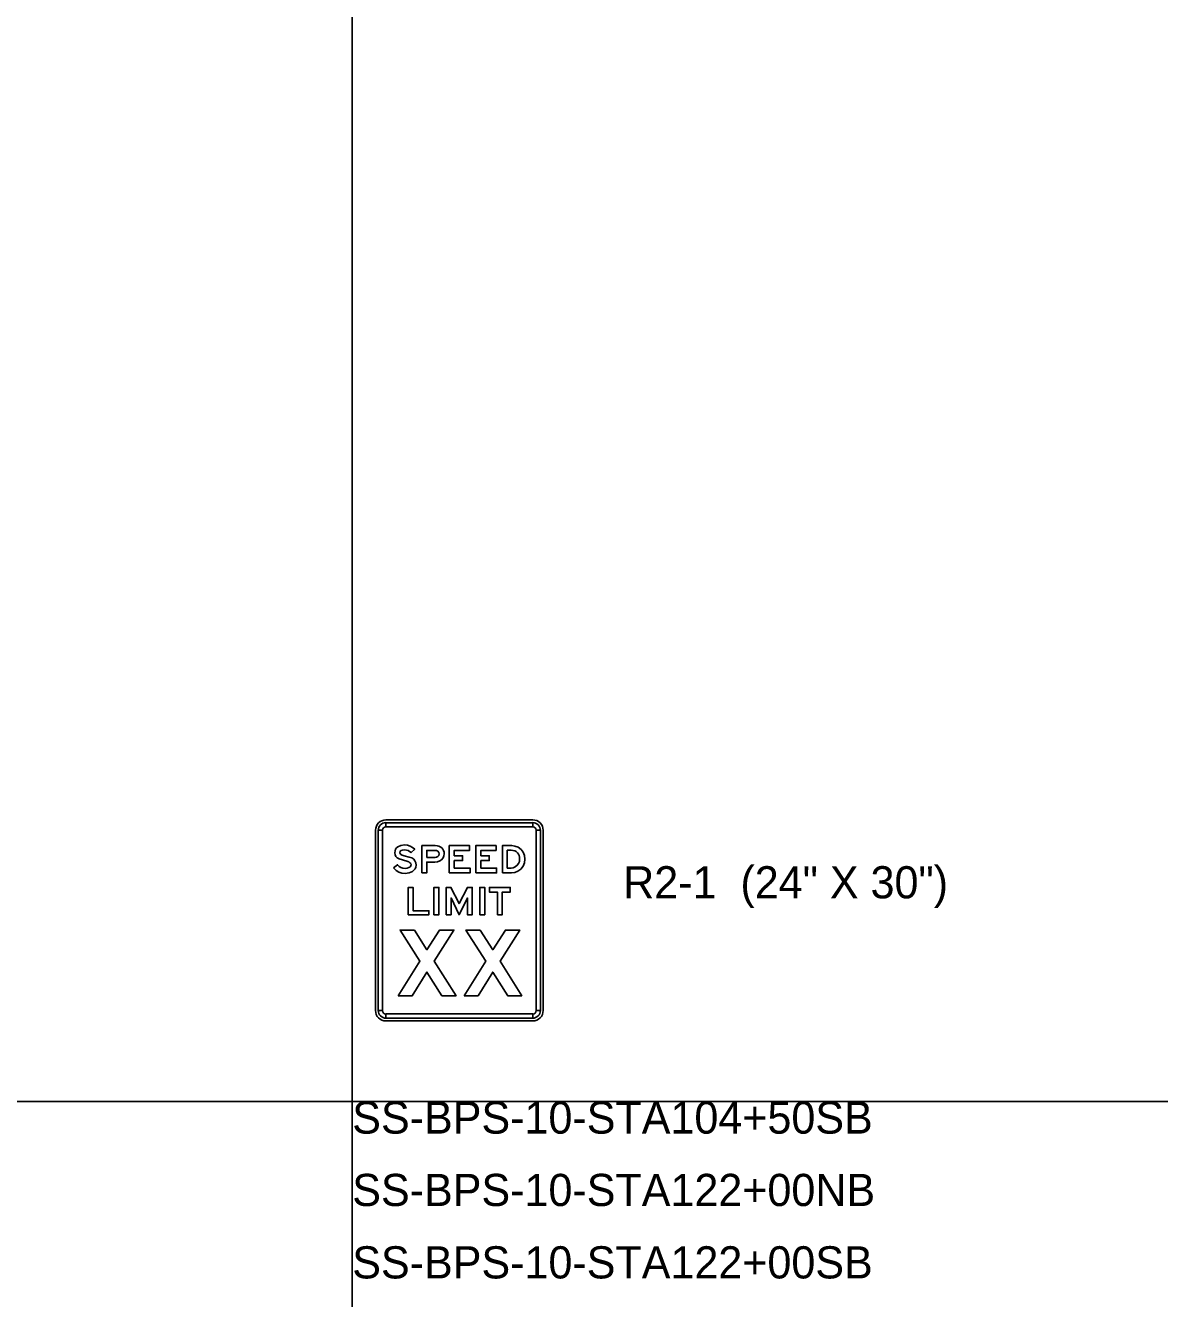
# Model space of a CAD drawing. Extents: x 1001568 to 1002149, y 1840825 to 1841423.
# Drawn here: x 1001914.59 to 1001928.68, y 1841079.02 to 1841094.84 of the extents above; entities that cross this region are included whole.
import ezdxf

# ---------------------------------------------------------------- set-up
doc = ezdxf.new("R2010")
doc.units = 0
for name, color, linetype in [('40', 7, 'Continuous'), ('R_No Plot', 7, 'Continuous'), ('SIGNS', 7, 'Continuous')]:
    doc.layers.add(name, color=color, linetype=linetype)

msp = doc.modelspace()

# ---------------------------------------------------------------- linework, layer by layer
at = {"layer": 'R_No Plot'}
for p, q in [((1001918.65, 1841110.667), (1001918.65, 1841048.127)), ((1001890.65, 1841081.469), (1001982.133, 1841081.469))]:
    msp.add_line(p, q, dxfattribs=at)
at = {"layer": 'SIGNS'}
for p, q in [((1001920.892, 1841084.969), (1001919.069, 1841084.969)), ((1001919.069, 1841084.882), (1001919.069, 1841084.934)), ((1001920.892, 1841084.934), (1001920.892, 1841084.882)), ((1001918.939, 1841084.839), (1001918.939, 1841082.599)), ((1001918.973, 1841084.839), (1001919.025, 1841084.839)), ((1001920.935, 1841084.839), (1001920.987, 1841084.839)), ((1001921.022, 1841082.599), (1001921.022, 1841084.839)), ((1001919.025, 1841082.599), (1001918.973, 1841082.599)), ((1001919.069, 1841082.504), (1001919.069, 1841082.556)), ((1001920.892, 1841082.556), (1001920.892, 1841082.504)), ((1001920.987, 1841082.599), (1001920.935, 1841082.599)), ((1001919.069, 1841082.469), (1001920.892, 1841082.469))]:
    msp.add_line(p, q, dxfattribs=at)
for points in [[(1001920.892, 1841084.934), (1001919.069, 1841084.934), (1001919.069, 1841084.882), (1001920.892, 1841084.882), (1001920.892, 1841084.934), (1001920.892, 1841084.934)], [(1001918.973, 1841084.839), (1001918.973, 1841082.599), (1001919.025, 1841082.599), (1001919.025, 1841084.839), (1001918.973, 1841084.839), (1001918.973, 1841084.839)], [(1001920.987, 1841082.599), (1001920.987, 1841084.839), (1001920.935, 1841084.839), (1001920.935, 1841082.599), (1001920.987, 1841082.599), (1001920.987, 1841082.599)], [(1001919.164, 1841084.371), (1001919.194, 1841084.341), (1001919.227, 1841084.32), (1001919.265, 1841084.307), (1001919.307, 1841084.303), (1001919.355, 1841084.309), (1001919.397, 1841084.328), (1001919.417, 1841084.343), (1001919.431, 1841084.361), (1001919.439, 1841084.382), (1001919.442, 1841084.405), (1001919.439, 1841084.434), (1001919.429, 1841084.458), (1001919.413, 1841084.479), (1001919.39, 1841084.495), (1001919.356, 1841084.507), (1001919.293, 1841084.523), (1001919.27, 1841084.53), (1001919.254, 1841084.539), (1001919.244, 1841084.549), (1001919.241, 1841084.561), (1001919.245, 1841084.576), (1001919.255, 1841084.587), (1001919.273, 1841084.594), (1001919.298, 1841084.596), (1001919.322, 1841084.594), (1001919.343, 1841084.588), (1001919.363, 1841084.577), (1001919.38, 1841084.562), (1001919.427, 1841084.603), (1001919.4, 1841084.627), (1001919.37, 1841084.643), (1001919.337, 1841084.653), (1001919.301, 1841084.657), (1001919.255, 1841084.651), (1001919.218, 1841084.634), (1001919.201, 1841084.62), (1001919.189, 1841084.603), (1001919.182, 1841084.583), (1001919.179, 1841084.561), (1001919.182, 1841084.536), (1001919.192, 1841084.515), (1001919.209, 1841084.497), (1001919.231, 1841084.483), (1001919.328, 1841084.454), (1001919.351, 1841084.446), (1001919.367, 1841084.436), (1001919.377, 1841084.425), (1001919.38, 1841084.412), (1001919.379, 1841084.401), (1001919.374, 1841084.391), (1001919.365, 1841084.383), (1001919.353, 1841084.376), (1001919.331, 1841084.369), (1001919.306, 1841084.366), (1001919.278, 1841084.369), (1001919.254, 1841084.377), (1001919.233, 1841084.391), (1001919.214, 1841084.411)], [(1001919.855, 1841084.309), (1001920.113, 1841084.309), (1001920.113, 1841084.369), (1001919.918, 1841084.369), (1001919.918, 1841084.463), (1001920.021, 1841084.463), (1001920.021, 1841084.523), (1001919.918, 1841084.523), (1001919.918, 1841084.59), (1001920.107, 1841084.59), (1001920.107, 1841084.65), (1001919.855, 1841084.65)], [(1001920.185, 1841084.309), (1001920.443, 1841084.309), (1001920.443, 1841084.369), (1001920.248, 1841084.369), (1001920.248, 1841084.463), (1001920.351, 1841084.463), (1001920.351, 1841084.523), (1001920.248, 1841084.523), (1001920.248, 1841084.59), (1001920.437, 1841084.59), (1001920.437, 1841084.65), (1001920.185, 1841084.65)], [(1001919.345, 1841083.789), (1001919.602, 1841083.789), (1001919.602, 1841083.84), (1001919.406, 1841083.84), (1001919.406, 1841084.129), (1001919.345, 1841084.129)], [(1001919.664, 1841083.789), (1001919.726, 1841083.789), (1001919.726, 1841084.129), (1001919.664, 1841084.129)], [(1001919.817, 1841083.789), (1001919.877, 1841083.789), (1001919.877, 1841083.998), (1001919.977, 1841083.789), (1001920.08, 1841083.998), (1001920.08, 1841083.789), (1001920.14, 1841083.789), (1001920.14, 1841084.129), (1001920.08, 1841084.129), (1001919.977, 1841083.928), (1001919.876, 1841084.129), (1001919.817, 1841084.129)], [(1001920.234, 1841083.789), (1001920.296, 1841083.789), (1001920.296, 1841084.129), (1001920.234, 1841084.129)], [(1001920.454, 1841083.789), (1001920.514, 1841083.789), (1001920.514, 1841084.072), (1001920.613, 1841084.072), (1001920.613, 1841084.129), (1001920.355, 1841084.129), (1001920.355, 1841084.072), (1001920.454, 1841084.072)], [(1001919.222, 1841082.782), (1001919.396, 1841082.782), (1001919.578, 1841083.076), (1001919.764, 1841082.782), (1001919.939, 1841082.782), (1001919.668, 1841083.213), (1001919.912, 1841083.599), (1001919.735, 1841083.599), (1001919.578, 1841083.355), (1001919.422, 1841083.599), (1001919.245, 1841083.599), (1001919.491, 1841083.213)], [(1001920.039, 1841082.782), (1001920.213, 1841082.782), (1001920.396, 1841083.076), (1001920.581, 1841082.782), (1001920.756, 1841082.782), (1001920.486, 1841083.213), (1001920.73, 1841083.599), (1001920.552, 1841083.599), (1001920.396, 1841083.355), (1001920.239, 1841083.599), (1001920.062, 1841083.599), (1001920.308, 1841083.213)], [(1001919.069, 1841082.504), (1001920.892, 1841082.504), (1001920.892, 1841082.556), (1001919.069, 1841082.556), (1001919.069, 1841082.504), (1001919.069, 1841082.504)]]:
    msp.add_lwpolyline(points, close=True, dxfattribs=at)
for points in [[(1001919.515, 1841084.309), (1001919.575, 1841084.309), (1001919.575, 1841084.445), (1001919.674, 1841084.445), (1001919.708, 1841084.448), (1001919.737, 1841084.458), (1001919.76, 1841084.474), (1001919.778, 1841084.496), (1001919.789, 1841084.522), (1001919.793, 1841084.548), (1001919.791, 1841084.569), (1001919.785, 1841084.588), (1001919.775, 1841084.606), (1001919.761, 1841084.621), (1001919.744, 1841084.634), (1001919.725, 1841084.643), (1001919.705, 1841084.648), (1001919.682, 1841084.65), (1001919.515, 1841084.65), (1001919.515, 1841084.309)], [(1001920.515, 1841084.309), (1001920.627, 1841084.309), (1001920.669, 1841084.315), (1001920.709, 1841084.331), (1001920.746, 1841084.358), (1001920.772, 1841084.392), (1001920.788, 1841084.433), (1001920.793, 1841084.481), (1001920.788, 1841084.528), (1001920.773, 1841084.569), (1001920.747, 1841084.602), (1001920.71, 1841084.628), (1001920.671, 1841084.644), (1001920.631, 1841084.65), (1001920.515, 1841084.65), (1001920.515, 1841084.309)], [(1001919.575, 1841084.503), (1001919.575, 1841084.59), (1001919.676, 1841084.59), (1001919.696, 1841084.587), (1001919.713, 1841084.579), (1001919.725, 1841084.565), (1001919.729, 1841084.546), (1001919.725, 1841084.528), (1001919.714, 1841084.515), (1001919.698, 1841084.506), (1001919.68, 1841084.503), (1001919.575, 1841084.503)], [(1001920.575, 1841084.37), (1001920.575, 1841084.592), (1001920.625, 1841084.592), (1001920.647, 1841084.59), (1001920.668, 1841084.584), (1001920.686, 1841084.574), (1001920.702, 1841084.56), (1001920.714, 1841084.544), (1001920.722, 1841084.526), (1001920.727, 1841084.505), (1001920.729, 1841084.482), (1001920.726, 1841084.451), (1001920.717, 1841084.425), (1001920.7, 1841084.404), (1001920.675, 1841084.385), (1001920.649, 1841084.374), (1001920.625, 1841084.37), (1001920.575, 1841084.37)]]:
    msp.add_lwpolyline(points, dxfattribs=at)
for centre, radius, start, end in [((1001919.069, 1841084.839), 0.13, 90.0002, 179.9998), ((1001919.069, 1841084.839), 0.0955, 90.0002, 179.9998), ((1001920.892, 1841084.839), 0.13, 0, 90.0002), ((1001920.892, 1841084.839), 0.0955, 0, 90.0002), ((1001919.069, 1841084.839), 0.0434, 90.0002, 179.9998), ((1001920.892, 1841084.839), 0.0434, 0, 90.0002), ((1001919.069, 1841082.599), 0.13, 179.9998, 270.0001), ((1001919.069, 1841082.599), 0.0955, 179.9998, 270.0001), ((1001919.069, 1841082.599), 0.0434, 179.9998, 270.0001), ((1001920.892, 1841082.599), 0.13, 270.0001, 0.0003), ((1001920.892, 1841082.599), 0.0955, 270.0001, 0.0003), ((1001920.892, 1841082.599), 0.0434, 270.0001, 0.0003)]:
    msp.add_arc(centre, radius, start, end, dxfattribs=at)

# ---------------------------------------------------------------- texts
at = {"layer": '40'}
for s, p in [('R2-1  (24" X 30")', (1001922.016, 1841083.993)), ('SS-BPS-10-STA104+50SB', (1001918.65, 1841081.069)), ('SS-BPS-10-STA122+00NB', (1001918.65, 1841080.169)), ('SS-BPS-10-STA122+00SB', (1001918.65, 1841079.269))]:
    msp.add_text(s, height=0.4, rotation=0, dxfattribs=at).set_placement(p)

doc.saveas('drawing.dxf')
